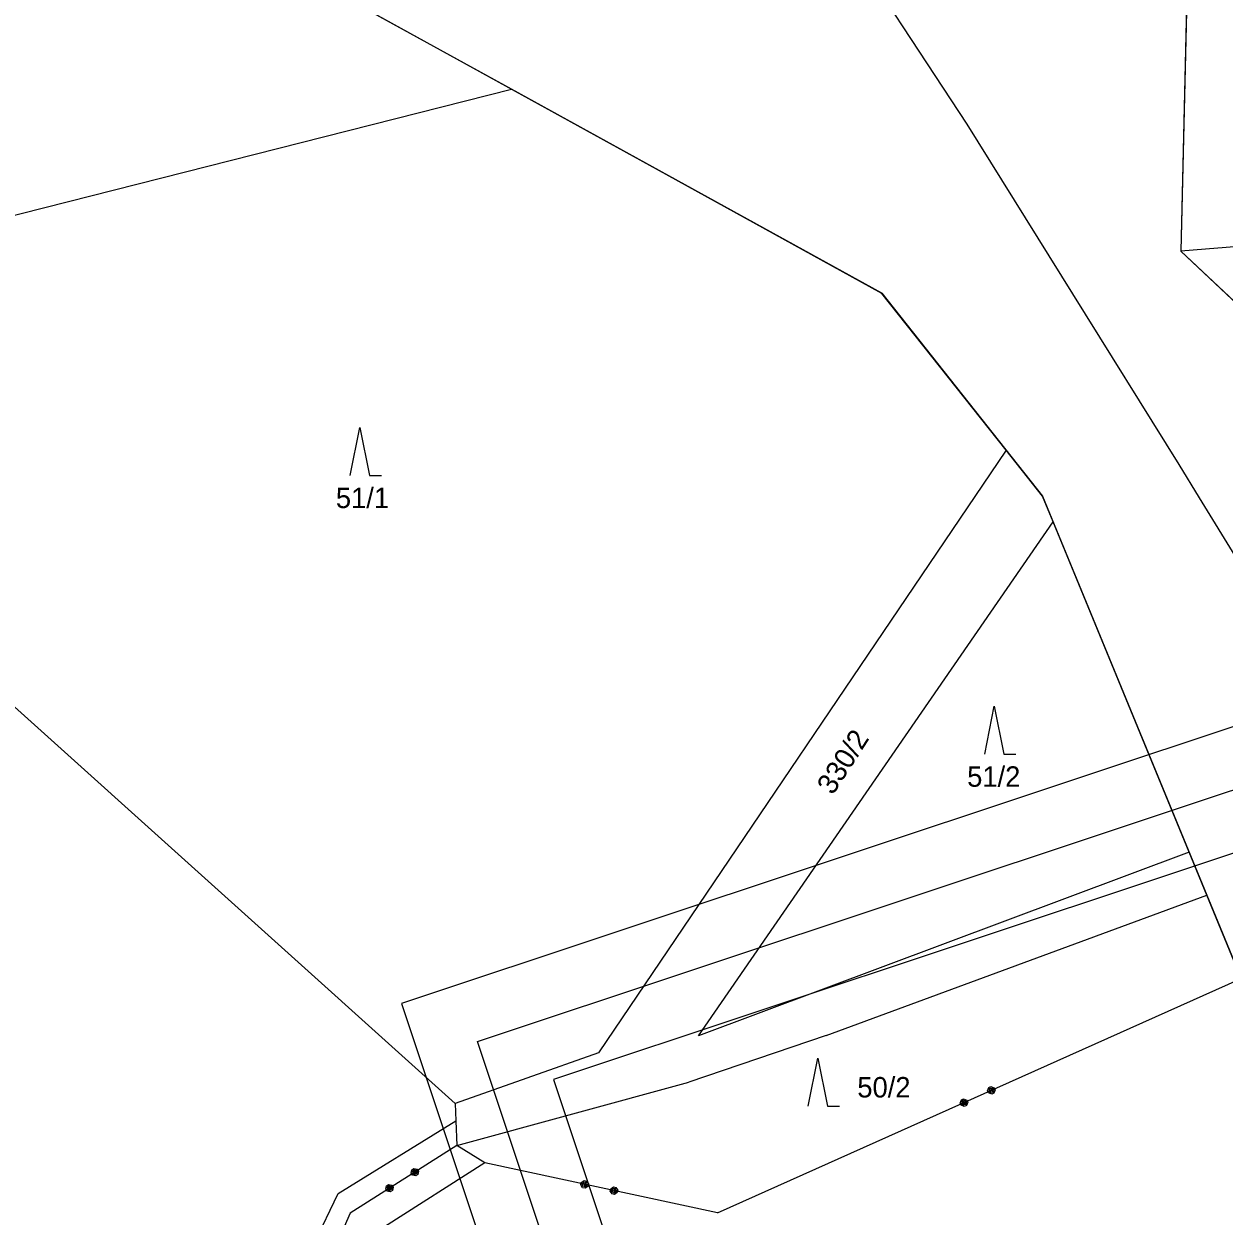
# Model space of a CAD drawing. Extents: x -866656 to -858817, y -1041816 to -1038653.
# Drawn here: x -864804.1 to -864704.3, y -1041373 to -1041273.8 of the extents above; entities that cross this region are included whole.
import ezdxf

# ---------------------------------------------------------------- set-up
doc = ezdxf.new("R2010")
doc.units = 0
for name, color, linetype in [('SZDC', 7, 'Continuous'), ('tisk ramy', 7, 'Continuous'), ('Vrstva 1', 7, 'Continuous'), ('Vrstva 3', 7, 'Continuous'), ('Vrstva 53', 7, 'Continuous')]:
    doc.layers.add(name, color=color, linetype=linetype)

msp = doc.modelspace()

# ---------------------------------------------------------------- linework, layer by layer
at = {"layer": 'SZDC'}
msp.add_lwpolyline([(-864806.24, -1041176.84), (-864798.286, -1041183.887), (-864794.374, -1041187.353), (-864782.521, -1041183.402), (-864771.624, -1041185.806), (-864744.425, -1041200.94), (-864739.358, -1041206.135), (-864711.79, -1041234.4), (-864706.957, -1041253.225), (-864707.405, -1041272.394), (-864707.88, -1041292.73), (-864695.12, -1041304.73), (-864665.06, -1041338.43), (-864702.863, -1041353.237), (-864705.721, -1041346.294), (-864707.188, -1041342.73), (-864718.497, -1041315.252), (-864719.377, -1041313.115), (-864722.414, -1041309.283), (-864732.75, -1041296.24), (-864763.526, -1041279.257), (-864778.41, -1041271.044), (-864800.939, -1041245.54), (-864805.267, -1041240.64)], dxfattribs=at)
at = {"layer": 'tisk ramy'}
for points in [[(-864678.843, -1041637.084), (-863881.875, -1041371.706), (-863975.703, -1041089.927), (-864772.671, -1041355.305)], [(-863888.199, -1041368.542), (-864675.679, -1041630.76), (-864766.347, -1041358.469), (-863978.867, -1041096.25)], [(-864672.518, -1041624.443), (-864089.016, -1041430.146), (-864176.529, -1041167.333), (-864760.03, -1041361.63)]]:
    msp.add_lwpolyline(points, close=True, dxfattribs=at)
at = {"layer": 'Vrstva 1'}
for p, q in [((-864706.957, -1041253.225), (-864707.88, -1041292.73)), ((-864778.41, -1041271.044), (-864732.75, -1041296.24)), ((-864840.33, -1041298.76), (-864763.526, -1041279.257)), ((-864695.79, -1041291.77), (-864707.88, -1041292.73)), ((-864707.88, -1041292.73), (-864695.12, -1041304.73)), ((-864732.75, -1041296.24), (-864719.377, -1041313.115)), ((-864768.21, -1041363.61), (-864840.33, -1041298.76)), ((-864776.94, -1041311.4), (-864776.14, -1041307.4)), ((-864776.14, -1041307.4), (-864775.34, -1041311.4)), ((-864722.414, -1041309.283), (-864756.3, -1041359.41)), ((-864775.34, -1041311.4), (-864774.34, -1041311.4)), ((-864719.377, -1041313.115), (-864702.863, -1041353.237)), ((-864747.97, -1041358), (-864718.497, -1041315.252)), ((-864724.19, -1041334.58), (-864723.39, -1041330.58)), ((-864723.39, -1041330.58), (-864722.59, -1041334.58)), ((-864722.59, -1041334.58), (-864721.59, -1041334.58)), ((-864707.188, -1041342.73), (-864747.97, -1041358)), ((-864737.36, -1041357.97), (-864705.721, -1041346.294)), ((-864737.36, -1041357.97), (-864748.79, -1041361.84)), ((-864756.3, -1041359.41), (-864768.21, -1041363.61)), ((-864738.87, -1041363.85), (-864738.07, -1041359.85)), ((-864738.07, -1041359.85), (-864737.27, -1041363.85)), ((-864768.07, -1041367.11), (-864748.79, -1041361.84)), ((-864768.21, -1041363.61), (-864768.17, -1041365.06)), ((-864737.27, -1041363.85), (-864736.27, -1041363.85)), ((-864777.94, -1041371.11), (-864768.17, -1041365.06)), ((-864768.17, -1041365.06), (-864768.07, -1041367.11)), ((-864765.76, -1041368.57), (-864774.08, -1041373.89)), ((-864790.81, -1041397.93), (-864777.94, -1041371.11))]:
    msp.add_line(p, q, dxfattribs=at)
for points in [[(-864819.104, -1041179.322), (-864806.398, -1041189.704), (-864793.161, -1041201.068), (-864778.246, -1041215.279), (-864766.368, -1041227.79), (-864755.038, -1041240.854), (-864744.469, -1041254.396), (-864737.015, -1041264.889), (-864725.662, -1041282.184), (-864716.892, -1041296.273)], [(-864716.892, -1041296.273), (-864708.057, -1041310.483), (-864706.352, -1041313.25), (-864684.947, -1041348.104)]]:
    msp.add_lwpolyline(points, dxfattribs=at)
at = {"layer": 'Vrstva 3'}
for p, q in [((-864746.41, -1041372.72), (-864702.863, -1041353.237)), ((-864746.41, -1041372.72), (-864702.863, -1041353.237)), ((-864723.947, -1041362.56), (-864723.846, -1041362.296)), ((-864723.947, -1041362.56), (-864723.846, -1041362.296)), ((-864723.865, -1041362.743), (-864723.947, -1041362.56)), ((-864723.865, -1041362.743), (-864723.947, -1041362.56)), ((-864723.856, -1041362.519), (-864723.774, -1041362.702)), ((-864723.856, -1041362.519), (-864723.774, -1041362.702)), ((-864723.846, -1041362.296), (-864723.664, -1041362.214)), ((-864723.846, -1041362.296), (-864723.664, -1041362.214)), ((-864723.805, -1041362.387), (-864723.623, -1041362.306)), ((-864723.805, -1041362.387), (-864723.623, -1041362.306)), ((-864723.642, -1041362.752), (-864723.805, -1041362.387)), ((-864723.642, -1041362.752), (-864723.805, -1041362.387)), ((-864723.714, -1041362.346), (-864723.551, -1041362.712)), ((-864723.714, -1041362.346), (-864723.551, -1041362.712)), ((-864723.664, -1041362.214), (-864723.399, -1041362.315)), ((-864723.664, -1041362.214), (-864723.399, -1041362.315)), ((-864723.623, -1041362.306), (-864723.459, -1041362.671)), ((-864723.623, -1041362.306), (-864723.459, -1041362.671)), ((-864723.409, -1041362.539), (-864723.491, -1041362.356)), ((-864723.409, -1041362.539), (-864723.491, -1041362.356)), ((-864723.459, -1041362.671), (-864723.409, -1041362.539)), ((-864723.459, -1041362.671), (-864723.409, -1041362.539)), ((-864723.318, -1041362.498), (-864723.419, -1041362.762)), ((-864723.318, -1041362.498), (-864723.419, -1041362.762)), ((-864723.399, -1041362.315), (-864723.318, -1041362.498)), ((-864723.399, -1041362.315), (-864723.318, -1041362.498)), ((-864726.229, -1041363.581), (-864726.128, -1041363.317)), ((-864726.229, -1041363.581), (-864726.128, -1041363.317)), ((-864726.147, -1041363.764), (-864726.229, -1041363.581)), ((-864726.147, -1041363.764), (-864726.229, -1041363.581)), ((-864726.138, -1041363.54), (-864726.056, -1041363.723)), ((-864726.138, -1041363.54), (-864726.056, -1041363.723)), ((-864726.128, -1041363.317), (-864725.946, -1041363.235)), ((-864726.128, -1041363.317), (-864725.946, -1041363.235)), ((-864726.087, -1041363.408), (-864725.905, -1041363.327)), ((-864726.087, -1041363.408), (-864725.905, -1041363.327)), ((-864725.924, -1041363.773), (-864726.087, -1041363.408)), ((-864725.924, -1041363.773), (-864726.087, -1041363.408)), ((-864725.996, -1041363.367), (-864725.833, -1041363.733)), ((-864725.996, -1041363.367), (-864725.833, -1041363.733)), ((-864725.946, -1041363.235), (-864725.681, -1041363.336)), ((-864725.946, -1041363.235), (-864725.681, -1041363.336)), ((-864725.905, -1041363.327), (-864725.741, -1041363.692)), ((-864725.905, -1041363.327), (-864725.741, -1041363.692)), ((-864725.691, -1041363.56), (-864725.773, -1041363.377)), ((-864725.691, -1041363.56), (-864725.773, -1041363.377)), ((-864725.741, -1041363.692), (-864725.691, -1041363.56)), ((-864725.741, -1041363.692), (-864725.691, -1041363.56)), ((-864725.6, -1041363.519), (-864725.701, -1041363.783)), ((-864725.6, -1041363.519), (-864725.701, -1041363.783)), ((-864725.681, -1041363.336), (-864725.6, -1041363.519)), ((-864725.681, -1041363.336), (-864725.6, -1041363.519)), ((-864723.601, -1041362.844), (-864723.865, -1041362.743)), ((-864723.601, -1041362.844), (-864723.865, -1041362.743)), ((-864723.774, -1041362.702), (-864723.642, -1041362.752)), ((-864723.774, -1041362.702), (-864723.642, -1041362.752)), ((-864723.419, -1041362.762), (-864723.601, -1041362.844)), ((-864723.419, -1041362.762), (-864723.601, -1041362.844)), ((-864725.883, -1041363.865), (-864726.147, -1041363.764)), ((-864725.883, -1041363.865), (-864726.147, -1041363.764)), ((-864726.056, -1041363.723), (-864725.924, -1041363.773)), ((-864726.056, -1041363.723), (-864725.924, -1041363.773)), ((-864725.701, -1041363.783), (-864725.883, -1041363.865)), ((-864725.701, -1041363.783), (-864725.883, -1041363.865)), ((-864768.07, -1041367.11), (-864776.93, -1041372.73)), ((-864768.07, -1041367.11), (-864776.93, -1041372.73)), ((-864765.76, -1041368.57), (-864768.07, -1041367.11)), ((-864765.76, -1041368.57), (-864768.07, -1041367.11)), ((-864746.41, -1041372.72), (-864765.76, -1041368.57)), ((-864746.41, -1041372.72), (-864765.76, -1041368.57)), ((-864771.878, -1041369.407), (-864771.816, -1041369.131)), ((-864771.878, -1041369.407), (-864771.816, -1041369.131)), ((-864771.77, -1041369.575), (-864771.878, -1041369.407)), ((-864771.77, -1041369.575), (-864771.878, -1041369.407)), ((-864771.816, -1041369.131), (-864771.647, -1041369.023)), ((-864771.816, -1041369.131), (-864771.647, -1041369.023)), ((-864771.793, -1041369.353), (-864771.686, -1041369.522)), ((-864771.793, -1041369.353), (-864771.686, -1041369.522)), ((-864771.494, -1041369.637), (-864771.77, -1041369.575)), ((-864771.494, -1041369.637), (-864771.77, -1041369.575)), ((-864771.762, -1041369.215), (-864771.593, -1041369.108)), ((-864771.762, -1041369.215), (-864771.593, -1041369.108)), ((-864771.548, -1041369.553), (-864771.762, -1041369.215)), ((-864771.548, -1041369.553), (-864771.762, -1041369.215)), ((-864771.686, -1041369.522), (-864771.548, -1041369.553)), ((-864771.686, -1041369.522), (-864771.548, -1041369.553)), ((-864771.678, -1041369.161), (-864771.463, -1041369.499)), ((-864771.678, -1041369.161), (-864771.463, -1041369.499)), ((-864771.647, -1041369.023), (-864771.371, -1041369.085)), ((-864771.647, -1041369.023), (-864771.371, -1041369.085)), ((-864771.593, -1041369.108), (-864771.379, -1041369.446)), ((-864771.593, -1041369.108), (-864771.379, -1041369.446)), ((-864771.325, -1041369.53), (-864771.494, -1041369.637)), ((-864771.325, -1041369.53), (-864771.494, -1041369.637)), ((-864771.348, -1041369.308), (-864771.455, -1041369.139)), ((-864771.348, -1041369.308), (-864771.455, -1041369.139)), ((-864771.379, -1041369.446), (-864771.348, -1041369.308)), ((-864771.379, -1041369.446), (-864771.348, -1041369.308)), ((-864771.371, -1041369.085), (-864771.264, -1041369.254)), ((-864771.371, -1041369.085), (-864771.264, -1041369.254)), ((-864771.264, -1041369.254), (-864771.325, -1041369.53)), ((-864771.264, -1041369.254), (-864771.325, -1041369.53)), ((-864773.989, -1041370.746), (-864773.927, -1041370.47)), ((-864773.989, -1041370.746), (-864773.927, -1041370.47)), ((-864773.927, -1041370.47), (-864773.758, -1041370.363)), ((-864773.927, -1041370.47), (-864773.758, -1041370.363)), ((-864773.873, -1041370.554), (-864773.704, -1041370.447)), ((-864773.873, -1041370.554), (-864773.704, -1041370.447)), ((-864773.659, -1041370.892), (-864773.873, -1041370.554)), ((-864773.659, -1041370.892), (-864773.873, -1041370.554)), ((-864773.789, -1041370.501), (-864773.575, -1041370.838)), ((-864773.789, -1041370.501), (-864773.575, -1041370.838)), ((-864773.758, -1041370.363), (-864773.482, -1041370.424)), ((-864773.758, -1041370.363), (-864773.482, -1041370.424)), ((-864773.704, -1041370.447), (-864773.49, -1041370.785)), ((-864773.704, -1041370.447), (-864773.49, -1041370.785)), ((-864773.459, -1041370.647), (-864773.566, -1041370.478)), ((-864773.459, -1041370.647), (-864773.566, -1041370.478)), ((-864773.482, -1041370.424), (-864773.375, -1041370.593)), ((-864773.482, -1041370.424), (-864773.375, -1041370.593)), ((-864773.375, -1041370.593), (-864773.437, -1041370.869)), ((-864773.375, -1041370.593), (-864773.437, -1041370.869)), ((-864757.768, -1041370.386), (-864757.726, -1041370.19)), ((-864757.768, -1041370.386), (-864757.726, -1041370.19)), ((-864757.614, -1041370.623), (-864757.768, -1041370.386)), ((-864757.614, -1041370.623), (-864757.768, -1041370.386)), ((-864757.726, -1041370.19), (-864757.488, -1041370.037)), ((-864757.726, -1041370.19), (-864757.488, -1041370.037)), ((-864757.628, -1041370.211), (-864757.67, -1041370.407)), ((-864757.628, -1041370.211), (-864757.67, -1041370.407)), ((-864757.67, -1041370.407), (-864757.593, -1041370.526)), ((-864757.67, -1041370.407), (-864757.593, -1041370.526)), ((-864757.419, -1041370.665), (-864757.614, -1041370.623)), ((-864757.419, -1041370.665), (-864757.614, -1041370.623)), ((-864757.593, -1041370.526), (-864757.509, -1041370.134)), ((-864757.593, -1041370.526), (-864757.509, -1041370.134)), ((-864757.509, -1041370.134), (-864757.314, -1041370.176)), ((-864757.509, -1041370.134), (-864757.314, -1041370.176)), ((-864757.411, -1041370.155), (-864757.495, -1041370.546)), ((-864757.411, -1041370.155), (-864757.495, -1041370.546)), ((-864757.488, -1041370.037), (-864757.293, -1041370.079)), ((-864757.488, -1041370.037), (-864757.293, -1041370.079)), ((-864757.181, -1041370.512), (-864757.419, -1041370.665)), ((-864757.181, -1041370.512), (-864757.419, -1041370.665)), ((-864757.314, -1041370.176), (-864757.398, -1041370.567)), ((-864757.314, -1041370.176), (-864757.398, -1041370.567)), ((-864757.398, -1041370.567), (-864757.279, -1041370.491)), ((-864757.398, -1041370.567), (-864757.279, -1041370.491)), ((-864757.293, -1041370.079), (-864757.139, -1041370.316)), ((-864757.293, -1041370.079), (-864757.139, -1041370.316)), ((-864757.279, -1041370.491), (-864757.237, -1041370.295)), ((-864757.279, -1041370.491), (-864757.237, -1041370.295)), ((-864757.139, -1041370.316), (-864757.181, -1041370.512)), ((-864757.139, -1041370.316), (-864757.181, -1041370.512)), ((-864755.281, -1041370.714), (-864755.044, -1041370.561)), ((-864755.281, -1041370.714), (-864755.044, -1041370.561)), ((-864755.044, -1041370.561), (-864754.848, -1041370.603)), ((-864755.044, -1041370.561), (-864754.848, -1041370.603)), ((-864754.848, -1041370.603), (-864754.695, -1041370.84)), ((-864754.848, -1041370.603), (-864754.695, -1041370.84)), ((-864773.882, -1041370.915), (-864773.989, -1041370.746)), ((-864773.882, -1041370.915), (-864773.989, -1041370.746)), ((-864773.904, -1041370.692), (-864773.797, -1041370.861)), ((-864773.904, -1041370.692), (-864773.797, -1041370.861)), ((-864773.605, -1041370.976), (-864773.882, -1041370.915)), ((-864773.605, -1041370.976), (-864773.882, -1041370.915)), ((-864773.797, -1041370.861), (-864773.659, -1041370.892)), ((-864773.797, -1041370.861), (-864773.659, -1041370.892)), ((-864773.437, -1041370.869), (-864773.605, -1041370.976)), ((-864773.437, -1041370.869), (-864773.605, -1041370.976)), ((-864773.49, -1041370.785), (-864773.459, -1041370.647)), ((-864773.49, -1041370.785), (-864773.459, -1041370.647)), ((-864755.323, -1041370.91), (-864755.281, -1041370.714)), ((-864755.323, -1041370.91), (-864755.281, -1041370.714)), ((-864755.17, -1041371.148), (-864755.323, -1041370.91)), ((-864755.17, -1041371.148), (-864755.323, -1041370.91)), ((-864755.184, -1041370.735), (-864755.225, -1041370.931)), ((-864755.184, -1041370.735), (-864755.225, -1041370.931)), ((-864755.225, -1041370.931), (-864755.149, -1041371.05)), ((-864755.225, -1041370.931), (-864755.149, -1041371.05)), ((-864754.974, -1041371.189), (-864755.17, -1041371.148)), ((-864754.974, -1041371.189), (-864755.17, -1041371.148)), ((-864755.149, -1041371.05), (-864755.065, -1041370.659)), ((-864755.149, -1041371.05), (-864755.065, -1041370.659)), ((-864755.065, -1041370.659), (-864754.869, -1041370.701)), ((-864755.065, -1041370.659), (-864754.869, -1041370.701)), ((-864754.967, -1041370.68), (-864755.051, -1041371.071)), ((-864754.967, -1041370.68), (-864755.051, -1041371.071)), ((-864754.737, -1041371.036), (-864754.974, -1041371.189)), ((-864754.737, -1041371.036), (-864754.974, -1041371.189)), ((-864754.869, -1041370.701), (-864754.953, -1041371.092)), ((-864754.869, -1041370.701), (-864754.953, -1041371.092)), ((-864754.953, -1041371.092), (-864754.834, -1041371.015)), ((-864754.953, -1041371.092), (-864754.834, -1041371.015)), ((-864754.834, -1041371.015), (-864754.792, -1041370.819)), ((-864754.834, -1041371.015), (-864754.792, -1041370.819)), ((-864754.695, -1041370.84), (-864754.737, -1041371.036)), ((-864754.695, -1041370.84), (-864754.737, -1041371.036)), ((-864776.93, -1041372.73), (-864788.2, -1041398)), ((-864776.93, -1041372.73), (-864788.2, -1041398))]:
    msp.add_line(p, q, dxfattribs=at)
at = {"layer": 'Vrstva 53'}
for points in [[(-864702.863, -1041353.237), (-864705.721, -1041346.294), (-864707.188, -1041342.73), (-864718.497, -1041315.253), (-864719.377, -1041313.116), (-864722.414, -1041309.283), (-864732.75, -1041296.241), (-864763.526, -1041279.258), (-864778.41, -1041271.045), (-864800.939, -1041245.54), (-864805.267, -1041240.641), (-864818.87, -1041192.671), (-864832.594, -1041200.466), (-864855.341, -1041203.106), (-864853.029, -1041195.924), (-864857.302, -1041194.593), (-864848.751, -1041173.216), (-864869.48, -1041156.301), (-864889.69, -1041132.821)], [(-864834.001, -1041135.622), (-864824.11, -1041144.811), (-864806.24, -1041176.841), (-864798.286, -1041183.888), (-864794.374, -1041187.354), (-864782.521, -1041183.403), (-864771.624, -1041185.807), (-864744.425, -1041200.941), (-864739.358, -1041206.135), (-864711.79, -1041234.401), (-864706.957, -1041253.226), (-864707.405, -1041272.394), (-864707.88, -1041292.731), (-864695.12, -1041304.731), (-864665.06, -1041338.43)]]:
    msp.add_lwpolyline(points, dxfattribs=at)

# ---------------------------------------------------------------- texts
at = {"layer": 'Vrstva 1'}
for s, p in [('51/1', (-864778.132, -1041314.1)), ('51/2', (-864725.645, -1041337.28)), ('50/2', (-864734.778, -1041363.12))]:
    msp.add_text(s, height=1.7, dxfattribs=at).set_placement(p)
msp.add_text('330/2', height=1.7, rotation=57.2517, dxfattribs=at).set_placement((-864736.817, -1041338.035))

doc.saveas('drawing.dxf')
